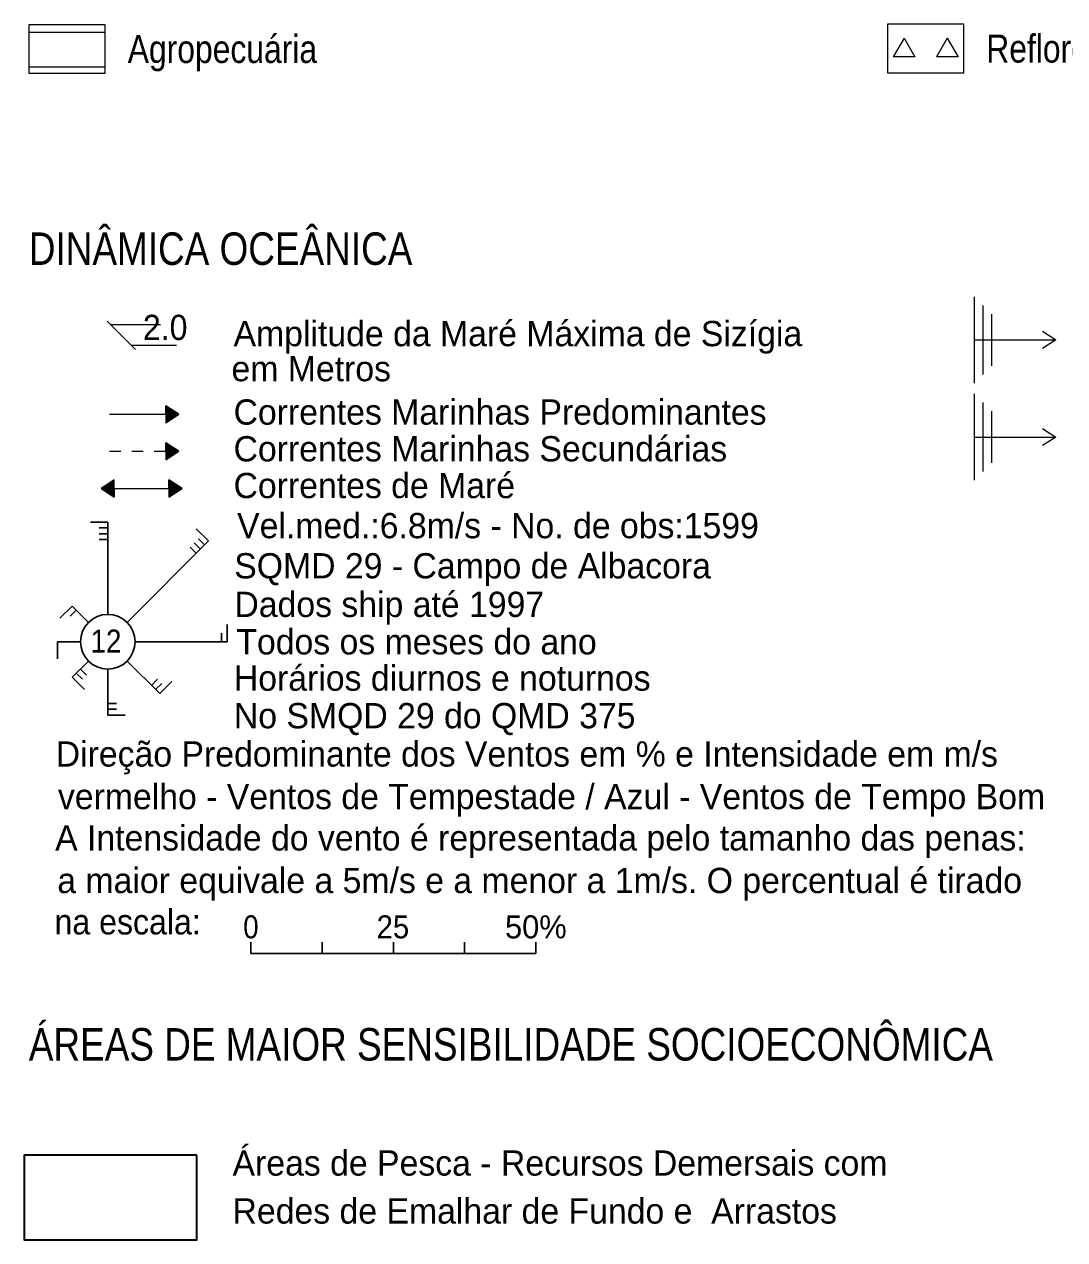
# Model space of a CAD drawing. Extents: x -6.3 to 58.7, y 19.8 to 60.6.
# Drawn here: x 34.51 to 43.55, y 39.89 to 50.44 of the extents above; entities that cross this region are included whole.
import ezdxf
from ezdxf.enums import TextEntityAlignment as Align

# ---------------------------------------------------------------- set-up
doc = ezdxf.new("R2010")
doc.units = 0
doc.header["$LTSCALE"] = 0.092
doc.layers.add('17', color=7, linetype='Continuous', lineweight=25)
doc.layers.add('58', color=7, linetype='Continuous', lineweight=13)

msp = doc.modelspace()

# ---------------------------------------------------------------- linework, layer by layer
at = {"layer": '17'}
for p, q in [((35.08568, 46.12024), (35.23568, 46.12024)), ((35.16068, 46.07023), (35.23568, 46.07023)), ((35.23568, 46.12024), (35.23568, 45.32023)), ((36.00463, 46.06386), (36.1107, 45.95779)), ((35.16068, 46.02023), (35.23568, 46.02023)), ((35.16068, 45.97023), (35.23568, 45.97023)), ((35.40359, 45.25069), (36.1107, 45.95779)), ((35.98695, 45.94012), (36.03999, 45.88708)), ((36.02231, 45.97547), (36.07534, 45.92244)), ((35.9516, 45.90476), (36.00463, 45.85173)), ((34.82033, 45.28601), (34.92639, 45.39207)), ((34.92639, 45.39207), (35.06778, 45.25069)), ((34.90872, 45.30368), (34.96175, 45.35672)), ((36.27314, 45.23278), (36.27314, 45.08278)), ((34.79823, 45.08278), (34.99823, 45.08278)), ((34.79823, 44.93278), (34.79823, 45.08278)), ((35.47314, 45.08278), (36.27314, 45.08278)), ((36.22314, 45.15778), (36.22314, 45.08278)), ((34.92636, 44.77345), (35.06778, 44.91488)), ((35.40359, 44.91488), (35.68643, 44.63203)), ((35.03242, 44.66739), (34.92636, 44.77345)), ((35.01475, 44.75578), (34.96171, 44.80881)), ((35.0501, 44.79113), (34.99707, 44.84416)), ((35.23568, 44.84533), (35.23568, 44.44533)), ((35.66876, 44.75578), (35.61572, 44.70274)), ((35.70411, 44.72042), (35.65108, 44.66739)), ((35.7925, 44.7381), (35.68643, 44.63203)), ((35.31068, 44.54533), (35.23568, 44.54533)), ((35.31068, 44.49533), (35.23568, 44.49533)), ((35.38568, 44.44533), (35.23568, 44.44533)), ((36.4793, 42.37379), (36.4793, 42.47379)), ((37.09803, 42.37379), (37.09803, 42.47379)), ((37.71676, 42.37379), (37.71676, 42.47379)), ((38.33548, 42.37379), (38.33548, 42.47379)), ((38.95421, 42.37379), (38.95421, 42.47379)), ((36.4793, 42.37379), (38.95421, 42.37379))]:
    msp.add_line(p, q, dxfattribs=at)
msp.add_circle((35.23568, 45.08278), 0.23745, dxfattribs=at)
at = {"layer": '58'}
for p, q in [((34.55088, 50.37724), (35.21254, 50.37724)), ((42.15401, 50.32418), (42.06002, 50.1614)), ((42.52995, 50.32418), (42.43596, 50.1614)), ((42.52995, 50.32418), (42.62393, 50.1614)), ((42.62393, 50.1614), (42.43596, 50.1614)), ((34.55088, 50.07649), (35.21254, 50.07649)), ((42.76325, 48.07756), (42.76325, 47.98084)), ((42.83808, 48.00273), (42.83808, 47.98084)), ((42.83808, 47.98084), (42.83808, 47.53326)), ((35.22934, 47.86731), (35.4771, 47.61956)), ((35.26041, 47.83634), (35.694, 47.83634)), ((43.35693, 47.77822), (43.47391, 47.70309)), ((35.44, 47.65684), (35.83335, 47.65684)), ((42.76323, 47.70336), (43.47337, 47.70336)), ((43.47391, 47.70309), (43.35693, 47.62859)), ((42.76325, 47.53326), (42.76325, 47.32928)), ((42.83808, 47.53326), (42.83808, 47.40412)), ((35.85392, 47.0576), (35.73908, 47.13246)), ((35.73908, 47.0576), (35.73908, 47.13246)), ((35.73908, 47.12611), (35.74874, 47.12611)), ((35.73908, 47.1186), (35.76037, 47.1186)), ((35.73908, 47.11109), (35.77181, 47.11109)), ((35.73908, 47.10366), (35.78326, 47.10366)), ((35.73908, 47.09615), (35.79471, 47.09615)), ((35.73908, 47.08864), (35.80634, 47.08864)), ((35.73908, 47.08122), (35.81779, 47.08122)), ((42.83818, 47.15967), (42.83818, 46.56105)), ((42.91295, 47.08481), (42.91295, 46.63582)), ((35.25021, 47.05796), (35.7364, 47.05796)), ((35.73872, 46.99115), (35.75178, 46.99115)), ((35.73898, 46.98275), (35.76275, 46.99823)), ((35.73908, 47.0737), (35.82923, 47.0737)), ((35.73908, 47.06619), (35.84068, 47.06619)), ((35.73908, 47.05877), (35.85231, 47.05877)), ((35.73908, 47.05125), (35.84426, 47.05125)), ((35.73908, 47.04374), (35.83263, 47.04374)), ((35.73908, 47.03632), (35.82118, 47.03632)), ((35.73908, 47.0288), (35.80974, 47.0288)), ((35.73908, 47.02138), (35.79829, 47.02138)), ((35.73908, 47.01387), (35.78666, 47.01387)), ((35.73908, 47.00644), (35.77521, 47.00644)), ((35.73908, 46.99893), (35.76376, 46.99893)), ((35.76275, 46.99823), (35.8539, 47.05758)), ((43.35693, 46.93518), (43.47391, 46.86005)), ((35.85392, 46.73634), (35.73908, 46.81111)), ((35.73908, 46.73634), (35.73908, 46.81111)), ((35.73908, 46.80476), (35.74874, 46.80476)), ((35.73908, 46.79725), (35.76037, 46.79725)), ((35.73908, 46.78991), (35.77181, 46.78991)), ((35.73908, 46.7824), (35.78326, 46.7824)), ((35.73908, 46.77489), (35.79471, 46.77489)), ((35.73908, 46.76738), (35.80634, 46.76738)), ((42.76323, 46.86032), (43.47337, 46.86032)), ((43.47391, 46.86005), (43.35693, 46.78554)), ((35.25021, 46.73598), (35.34752, 46.73598)), ((35.44501, 46.73598), (35.54232, 46.73598)), ((35.6398, 46.73598), (35.7364, 46.73598)), ((35.73908, 46.75995), (35.81779, 46.75995)), ((35.73908, 46.75244), (35.82923, 46.75244)), ((35.73908, 46.74493), (35.84068, 46.74493)), ((35.73908, 46.7375), (35.85231, 46.7375)), ((35.73908, 46.66148), (35.85392, 46.73634)), ((35.73908, 46.73634), (35.73908, 46.66148)), ((35.73908, 46.72999), (35.84426, 46.72999)), ((35.73908, 46.72248), (35.83263, 46.72248)), ((35.73908, 46.71505), (35.82118, 46.71505)), ((35.73908, 46.70754), (35.80974, 46.70754)), ((35.73908, 46.70003), (35.79829, 46.70003)), ((35.73908, 46.69252), (35.78666, 46.69252)), ((35.73908, 46.68509), (35.77521, 46.68509)), ((35.73908, 46.67758), (35.76376, 46.67758)), ((35.73908, 46.67007), (35.75232, 46.67007)), ((35.73908, 46.66264), (35.74069, 46.66264)), ((35.29207, 46.48886), (35.17723, 46.41409)), ((35.29207, 46.45032), (35.23286, 46.45032)), ((35.29207, 46.45783), (35.24449, 46.45783)), ((35.29207, 46.46534), (35.25593, 46.46534)), ((35.29207, 46.47277), (35.26738, 46.47277)), ((35.29207, 46.48028), (35.27901, 46.48028)), ((35.29207, 46.48779), (35.29046, 46.48779)), ((35.29207, 46.41409), (35.29207, 46.48886)), ((35.76734, 46.41356), (35.76734, 46.48842)), ((35.88236, 46.41356), (35.76734, 46.48842)), ((35.76734, 46.48207), (35.77718, 46.48207)), ((35.76734, 46.47455), (35.78863, 46.47455)), ((35.76734, 46.46713), (35.80008, 46.46713)), ((35.76734, 46.45962), (35.8117, 46.45962)), ((35.76734, 46.45211), (35.82315, 46.45211)), ((35.76734, 46.44459), (35.8346, 46.44459)), ((35.17723, 46.41409), (35.29207, 46.33923)), ((35.29207, 46.41302), (35.17884, 46.41302)), ((35.29207, 46.42044), (35.18689, 46.42044)), ((35.29207, 46.40551), (35.19046, 46.40551)), ((35.29207, 46.42796), (35.19851, 46.42796)), ((35.29207, 46.398), (35.20191, 46.398)), ((35.29207, 46.43547), (35.20996, 46.43547)), ((35.29207, 46.39057), (35.21336, 46.39057)), ((35.29207, 46.44298), (35.22141, 46.44298)), ((35.29207, 46.38306), (35.22499, 46.38306)), ((35.29207, 46.37555), (35.23644, 46.37555)), ((35.29207, 46.36812), (35.24788, 46.36812)), ((35.29207, 46.36061), (35.25933, 46.36061)), ((35.29207, 46.3531), (35.27096, 46.3531)), ((35.28098, 46.41356), (35.76734, 46.41356)), ((35.29207, 46.34558), (35.28241, 46.34558)), ((35.29207, 46.41409), (35.29207, 46.33923)), ((35.76734, 46.43717), (35.84605, 46.43717)), ((35.76734, 46.42966), (35.85767, 46.42966)), ((35.76734, 46.42214), (35.86912, 46.42214)), ((35.76734, 46.41472), (35.88057, 46.41472)), ((35.76734, 46.41356), (35.76734, 46.3387)), ((35.76734, 46.3387), (35.88236, 46.41356)), ((35.76734, 46.40721), (35.87252, 46.40721)), ((35.76734, 46.39969), (35.86107, 46.39969)), ((35.76734, 46.39227), (35.84963, 46.39227)), ((35.76734, 46.38476), (35.838, 46.38476)), ((35.76734, 46.37725), (35.82655, 46.37725)), ((35.76734, 46.36973), (35.8151, 46.36973)), ((35.76734, 46.36231), (35.80365, 46.36231)), ((35.76734, 46.3548), (35.79203, 46.3548)), ((35.76734, 46.34728), (35.78058, 46.34728)), ((35.76734, 46.33986), (35.76913, 46.33986))]:
    msp.add_line(p, q, dxfattribs=at)
for points in [[(34.55088, 50.44076), (34.55088, 50.0197), (35.21254, 50.0197), (35.21254, 50.44076)], [(42.01045, 50.44462), (42.01045, 50.02356), (42.67211, 50.02356), (42.67211, 50.44462)]]:
    msp.add_lwpolyline(points, close=True, dxfattribs=at)
for points in [[(42.15401, 50.32418), (42.24799, 50.1614), (42.06002, 50.1614)], [(42.76325, 47.98084), (42.76325, 47.70342), (42.76325, 47.53326)], [(42.91291, 47.92791), (42.91291, 47.53326), (42.91291, 47.47894)], [(42.76325, 47.23452), (42.76325, 46.86039), (42.76325, 46.55325), (42.76325, 46.48624)], [(35.73898, 47.05758), (35.73898, 46.99823), (35.73898, 46.98275)]]:
    msp.add_lwpolyline(points, dxfattribs=at)
at = {"layer": '58', "lineweight": 35}
msp.add_lwpolyline([(36.00994, 40.6241), (34.51013, 40.6241), (34.51013, 39.88906), (36.00994, 39.88906)], close=True, dxfattribs=at)

# ---------------------------------------------------------------- texts
at = {"layer": '17'}
for s, width, p in [('12', 0.9, (35.22006, 44.98799)), ('0', 0.9, (36.4793, 42.50601)), ('25', 0.95, (37.71302, 42.50601))]:
    msp.add_text(s, height=0.2, dxfattribs=dict(at, width=width)).set_placement(p, align=Align.CENTER)
msp.add_text('50%', height=0.2, dxfattribs=at).set_placement((38.95481, 42.50601), align=Align.CENTER)
at = {"layer": '58'}
for s, height, width, p in [('Agropecuária', 0.2434, 0.85, (35.40871, 50.10854)), ('Reflorestamento', 0.2434, 0.85, (42.86828, 50.1124)), ('DINÂMICA OCEÂNICA', 0.2822, 0.85, (34.54936, 48.35511)), ('2.0', 0.2194, 0.95, (35.54062, 47.70254)), ('na escala:', 0.2194, 0.95, (34.7729, 42.54008)), ('ÁREAS DE MAIOR SENSIBILIDADE SOCIOECONÔMICA', 0.2822, 0.85, (34.54936, 41.44478))]:
    msp.add_text(s, height=height, dxfattribs=dict(at, width=width)).set_placement(p)
for s, p in [('Amplitude da Maré Máxima de Sizígia', (36.3283, 47.64898)), ('em Metros', (36.31041, 47.34453)), ('Correntes Marinhas Predominantes', (36.3283, 46.96755)), ('Correntes Marinhas Secundárias', (36.3283, 46.64853)), ('Correntes de Maré', (36.3283, 46.32941)), ('Vel.med.:6.8m/s - No. de obs:1599', (36.3592, 45.98117)), ('SQMD 29 - Campo de Albacora', (36.33411, 45.63219)), ('Dados ship até 1997', (36.33572, 45.29735)), ('Todos os meses do ano', (36.35244, 44.97238)), ('Horários diurnos e noturnos', (36.33114, 44.6569)), ('No SMQD 29 do QMD 375', (36.33114, 44.33056)), ('Direção Predominante dos Ventos em % e Intensidade em m/s', (34.78333, 43.99802)), ('vermelho - Ventos de Tempestade / Azul - Ventos de Tempo Bom', (34.80236, 43.62814)), ('A Intensidade do vento é representada pelo tamanho das penas:', (34.77811, 43.26905)), ('a maior equivale a 5m/s e a menor a 1m/s. O percentual é tirado', (34.79715, 42.89917)), ('Áreas de Pesca - Recursos Demersais com', (36.31943, 40.44536)), ('Redes de Emalhar de Fundo e  Arrastos', (36.31943, 40.02876))]:
    msp.add_text(s, height=0.2194, dxfattribs=at).set_placement(p)

doc.saveas('drawing.dxf')
